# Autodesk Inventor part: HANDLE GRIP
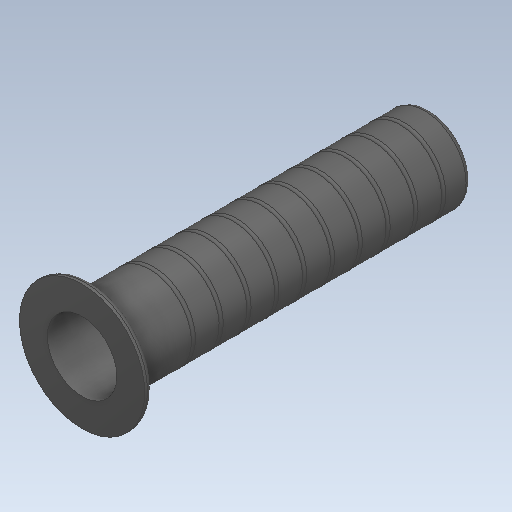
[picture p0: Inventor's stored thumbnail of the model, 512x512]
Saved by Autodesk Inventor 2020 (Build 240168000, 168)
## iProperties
Created: 1900-01
Part Number: HANDLE GRIP
Material: Générique
Document SubType Name: Modeling
Designer: bruno
Density: 1 g/cm^3
Appearance: Par défaut
Author: bruno
Revision Number: ANYUNSPECIFIED
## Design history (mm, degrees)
feature "Base1"
node "Solide1"
